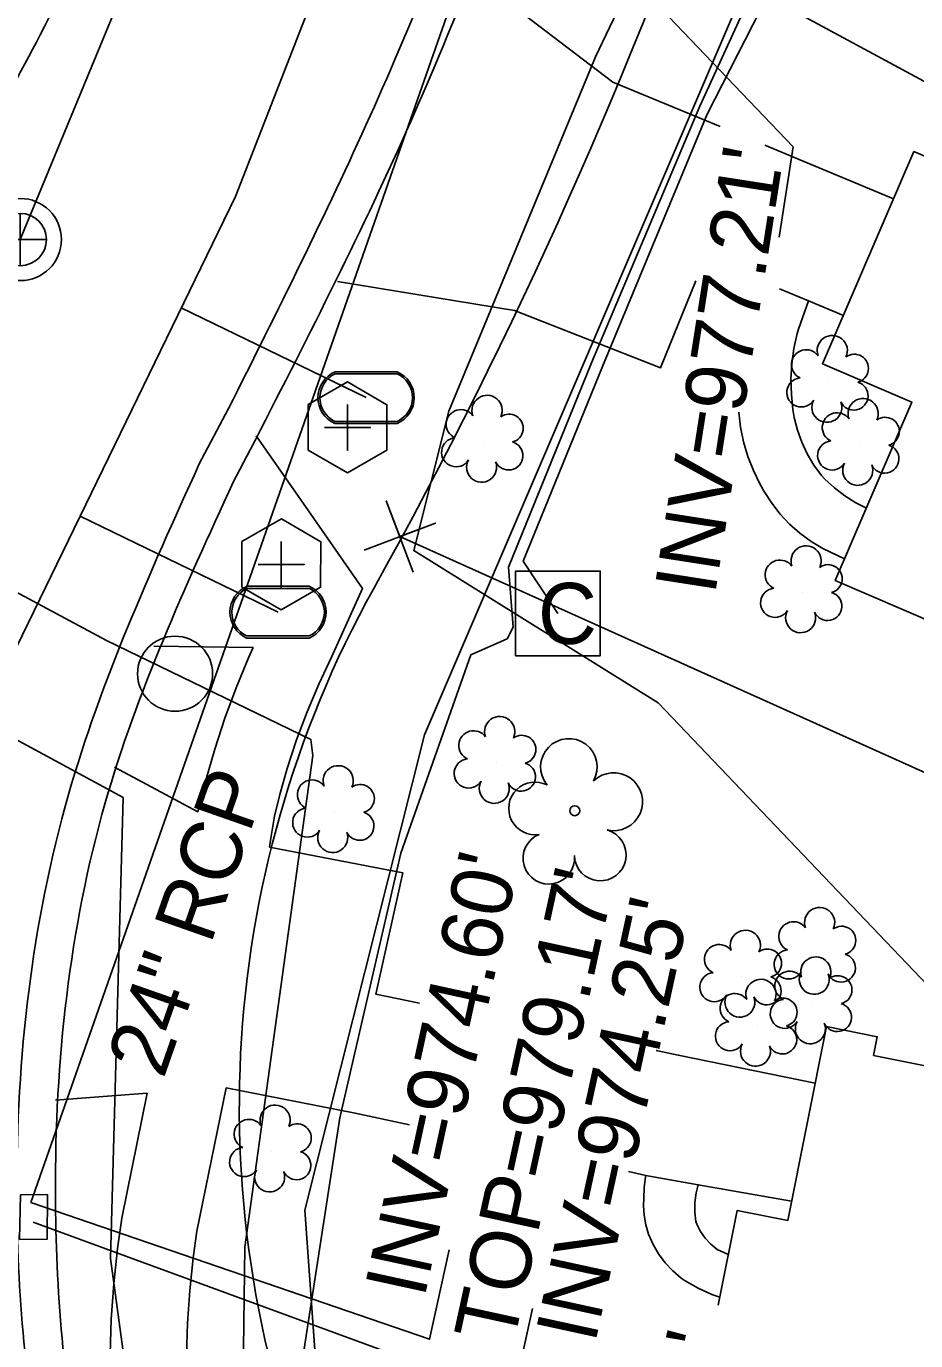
# Model space of a CAD drawing. Extents: x 1614427 to 1617186, y 896524 to 905462.
# Drawn here: x 1616388.5 to 1616446.8, y 901812.5 to 901898.7 of the extents above; entities that cross this region are included whole.
import ezdxf

# ---------------------------------------------------------------- set-up
doc = ezdxf.new("R2010")
doc.units = 0
for name, color, linetype in [('Exist Building', 7, 'Continuous'), ('Exist Other Culture Area Outline', 7, 'Continuous'), ('Exist Property Corner CELL', 7, 'Continuous'), ('Exist Property Line', 7, 'Continuous'), ('Exist Right of Way Line', 7, 'Continuous'), ('Exist Roads Curbs', 7, 'Continuous'), ('Exist Roads EOP', 7, 'Continuous'), ('Exist Roads EOP Other', 7, 'Continuous'), ('Exist Structure Minor Catch Basin', 7, 'Continuous'), ('Exist Structure Minor Catch Basin Leader', 7, 'Continuous'), ('Exist Structure Minor Catch Basin Top Elevation', 7, 'Continuous'), ('Exist Structure Minor Pipes RCP 18 Inch Invert', 7, 'Continuous'), ('Exist Structure Minor Pipes RCP 24 Inch', 7, 'Continuous'), ('Exist Structure Minor Pipes RCP 24 Inch Invert', 7, 'Continuous'), ('Exist Structure Minor Pipes RCP 24 Inch Leader', 7, 'Continuous'), ('Exist Structure Minor Pipes RCP 24 Inch Text', 7, 'Continuous'), ('Exist Utilities Gas UG Line SUE LOS B', 7, 'Continuous'), ('Exist Utilities Other Pole CELL', 7, 'Continuous'), ('Exist Utilities Power UG Cable SUE LOS B', 7, 'Continuous'), ('Exist Utilities Sanitary Sewer Clean-Out CELL', 7, 'Continuous'), ('Exist Utilities Sanitary Sewer Manhole CELL', 7, 'Continuous'), ('Exist Utilities Sanitary Sewer UG Line', 7, 'Continuous'), ('Exist Utilities Telephone UG FO SUE LOS B', 7, 'Continuous'), ('Exist Utilities TV Pedestal CELL', 7, 'Continuous'), ('Exist Utilities TV UG Cable SUE LOS B', 7, 'Continuous'), ('Exist Utilities Water Meter CELL', 7, 'Continuous'), ('Exist Utilities Water UG Line SUE LOS B', 7, 'Continuous'), ('Exist Vegetation Shrub CELL', 7, 'Continuous'), ('Exist Vegetation Tree CELL', 7, 'Continuous')]:
    doc.layers.add(name, color=color, linetype=linetype)

# ---------------------------------------------------------------- blocks, each defined once
blk = doc.blocks.new('EXIST UTILITIES SANITARY SEWER MANHOLE')
at = {"layer": 'Exist Utilities Sanitary Sewer Manhole CELL'}
blk.add_lwpolyline([(0, 0.03425), (0, -0.03425), (0, 0), (0.03425, 0), (-0.03425, 0)], dxfattribs=at)
for radius in [0.05389, 0.03425]:
    blk.add_circle((0, 0), radius, dxfattribs=at)
blk = doc.blocks.new('EXIST UTILITIES SANITARY SEWER CLEAN-OUT')
at = {"layer": 'Exist Utilities Sanitary Sewer Clean-Out CELL'}
blk.add_line((0, 0), (0, 0), dxfattribs=at)
blk.add_lwpolyline([(-0.0516, 0.0299), (-0.0517, -0.0297), (-0.0001, -0.0596), (0.0516, -0.0299), (0.0517, 0.0297), (0.0001, 0.0596)], close=True, dxfattribs=at)
blk.add_lwpolyline([(0, 0.0302), (0, -0.0302), (0, 0), (0.0302, 0), (-0.0302, 0)], dxfattribs=at)
blk = doc.blocks.new('EXIST UTILITIES WATER METER')
at = {"layer": 'Exist Utilities Water Meter CELL'}
blk.add_line((0, 0), (0, 0), dxfattribs=at)
for points in [[(-0.0408, 0.034), (0.0408, 0.034)], [(-0.0408, 0.0312), (0.0408, 0.0312)], [(0.0408, -0.0312), (-0.0413, -0.0312)], [(0.0408, -0.034), (-0.0413, -0.034)]]:
    blk.add_lwpolyline(points, dxfattribs=at)
for centre, radius, start, end in [((-0.0261, -0.0001), 0.0371, 113.178, 245.9794), ((-0.0259, -0.0001), 0.0347, 115.3009, 243.7824), ((0.0259, 0), 0.0371, 293.6483, 66.3084), ((0.0261, 0), 0.0345, 295.1272, 64.8728)]:
    blk.add_arc(centre, radius, start, end, dxfattribs=at)

msp = doc.modelspace()

# ---------------------------------------------------------------- linework, layer by layer
at = {"layer": 'Exist Building'}
msp.add_lwpolyline([(1616485.615, 901872.52), (1616475.033, 901847.931), (1616441.496, 901862.364), (1616446.524, 901874.046), (1616440.661, 901876.569), (1616446.648, 901890.482), (1616459.256, 901885.056), (1616458.823, 901884.049)], close=True, dxfattribs=at)
msp.add_lwpolyline([(1616433.826, 901814.822), (1616435.073, 901821.049), (1616438.374, 901820.388), (1616440.921, 901833.102), (1616444.246, 901832.436), (1616444.001, 901831.209), (1616477.737, 901824.452), (1616470.911, 901790.367), (1616437.689, 901797.02)], dxfattribs=at)
at = {"layer": 'Exist Other Culture Area Outline'}
for points in [[(1616443.537, 901867.106), (1616442.85, 901867.451), (1616442.12, 901867.907), (1616441.436, 901868.428), (1616440.803, 901869.009), (1616440.586, 901869.234), (1616440.09, 901869.921), (1616439.66, 901870.652), (1616439.302, 901871.419), (1616439.017, 901872.217), (1616438.808, 901873.038), (1616438.718, 901873.558), (1616438.615, 901874.558), (1616438.591, 901875.563), (1616438.647, 901876.567), (1616438.781, 901877.563), (1616438.994, 901878.545), (1616439.073, 901878.837), (1616439.738, 901880.686)], [(1616442.106, 901863.781), (1616440.675, 901864.444), (1616439.905, 901864.917), (1616439.179, 901865.455), (1616438.504, 901866.056), (1616437.885, 901866.714), (1616437.326, 901867.424), (1616436.832, 901868.181), (1616436.554, 901868.683), (1616436.125, 901869.572), (1616435.769, 901870.493), (1616435.488, 901871.44), (1616435.285, 901872.406), (1616435.161, 901873.386)], [(1616433.932, 901815.352), (1616433.412, 901815.541), (1616432.51, 901815.954), (1616431.645, 901816.438), (1616431.392, 901816.598), (1616430.842, 901817.072), (1616430.347, 901817.604), (1616429.914, 901818.187), (1616429.547, 901818.814), (1616429.25, 901819.478), (1616429.248, 901819.483), (1616429.067, 901820.093), (1616428.959, 901820.723), (1616428.925, 901821.364), (1616428.947, 901821.835), (1616428.958, 901822.549), (1616429.049, 901823.257), (1616429.065, 901823.344)], [(1616434.496, 901818.165), (1616434.391, 901818.204), (1616433.758, 901818.488), (1616433.334, 901818.823), (1616432.964, 901819.217), (1616432.655, 901819.66), (1616432.416, 901820.144), (1616432.354, 901820.31), (1616432.28, 901820.936), (1616432.285, 901821.566), (1616432.369, 901822.192), (1616432.508, 901822.728)]]:
    msp.add_lwpolyline(points, dxfattribs=at)
at = {"layer": 'Exist Property Corner CELL'}
msp.add_line((1616412.941, 901865.238), (1616412.941, 901865.238), dxfattribs=at)
msp.add_lwpolyline([(1616410.603, 901864.351), (1616415.278, 901866.125), (1616412.941, 901865.238), (1616412.054, 901867.575), (1616413.828, 901862.901)], dxfattribs=at)
at = {"layer": 'Exist Property Line'}
msp.add_line((1616412.941, 901865.238), (1616523.619, 901815.452), dxfattribs=at)
at = {"layer": 'Exist Right of Way Line'}
for centre, radius, start, end in [((1616126.099, 902020.281), 326.203, 330.93872, 10.91752), ((1616126.099, 902020.281), 276.203, 327.72922, 10.91752), ((1616472.42, 901827.828), 70, 150.93872, 203.3099)]:
    msp.add_arc(centre, radius, start, end, dxfattribs=at)
at = {"layer": 'Exist Roads Curbs'}
msp.add_line((1616402.021, 901868.809), (1616403.142, 901870.93), dxfattribs=at)
for points in [[(1616343.847, 901854.746), (1616355.943, 901862.067), (1616368.501, 901872.393), (1616373.628, 901878.463), (1616378.386, 901885.019), (1616387.13, 901899.385), (1616395.314, 901918.936), (1616406.85, 901957.62), (1616412.356, 901991.094), (1616413.858, 902015.925), (1616413.398, 902037.306), (1616411.493, 902057.132), (1616407.667, 902079.148)], [(1616403.142, 901870.93), (1616413.385, 901891.845), (1616421.355, 901911.815), (1616433.371, 901951.993), (1616439.135, 901988.052), (1616440.789, 902029.724), (1616437.241, 902067.23)], [(1616395.948, 901788.672), (1616392.138, 901803.31), (1616390.361, 901822.155), (1616393.632, 901847.778), (1616402.021, 901868.809)]]:
    msp.add_spline(points, degree=3, dxfattribs=at)
at = {"layer": 'Exist Roads EOP'}
msp.add_line((1616399.776, 901869.959), (1616401.72, 901873.638), dxfattribs=at)
for points in [[(1616345.045, 901852.485), (1616357.275, 901859.926), (1616370.331, 901870.605), (1616375.575, 901876.911), (1616380.419, 901883.477), (1616389.358, 901898.133), (1616397.69, 901918.06), (1616408.499, 901953.715), (1616414.808, 901990.97), (1616416.441, 902015.802), (1616415.921, 902037.434), (1616414.065, 902057.335), (1616410.189, 902079.521)], [(1616401.72, 901873.638), (1616410.999, 901892.827), (1616419.064, 901912.725), (1616430.933, 901952.504), (1616436.821, 901988.482), (1616438.3, 902029.711), (1616434.891, 902066.362)], [(1616393.549, 901788.008), (1616389.707, 901802.759), (1616387.829, 901822.202), (1616391.221, 901848.32), (1616399.776, 901869.959)]]:
    msp.add_spline(points, degree=3, dxfattribs=at)
at = {"layer": 'Exist Roads EOP Other'}
for points in [[(1616433.947, 901892.125), (1616426.919, 901895.044), (1616417.675, 901902.093)], [(1616445.315, 901887.384), (1616436.883, 901890.904)], [(1616432.357, 901882.001), (1616430.045, 901876.308), (1616420.459, 901880.059), (1616408.855, 901881.965)], [(1616442.024, 901879.737), (1616439.738, 901880.686), (1616437.835, 901881.476)], [(1616403.523, 901871.847), (1616406.953, 901866.924), (1616410.488, 901861.837), (1616408.47, 901857.329), (1616407.633, 901855.55), (1616406.868, 901853.739), (1616406.177, 901851.898), (1616405.561, 901850.031), (1616405.066, 901848.312), (1616404.736, 901846.893), (1616404.483, 901845.459), (1616404.401, 901844.868), (1616413.131, 901843.184), (1616411.372, 901835.217), (1616414.233, 901834.647)], [(1616394.235, 901850.114), (1616399.707, 901847.19), (1616400.218, 901849.256), (1616400.807, 901851.301), (1616401.472, 901853.323), (1616402.213, 901855.318), (1616403.028, 901857.284), (1616403.325, 901857.952), (1616396.823, 901858.049)], [(1616429.745, 901831.531), (1616431.2, 901831.235), (1616440.178, 901829.396)], [(1616390.376, 901828.272), (1616393.487, 901828.525), (1616396.383, 901828.74)], [(1616393.956, 901811.626), (1616394.028, 901813.912), (1616394.188, 901816.239), (1616394.433, 901818.55), (1616394.711, 901820.532), (1616396.383, 901828.74)], [(1616401.553, 901829.073), (1616399.641, 901819.685), (1616399.396, 901817.939), (1616399.17, 901815.804), (1616399.023, 901813.661), (1616398.955, 901811.515)], [(1616401.553, 901829.073), (1616410.011, 901827.426), (1616413.581, 901826.665)], [(1616427.936, 901823.589), (1616429.065, 901823.344), (1616429.315, 901823.29), (1616432.508, 901822.728), (1616438.627, 901821.65)]]:
    msp.add_lwpolyline(points, dxfattribs=at)
at = {"layer": 'Exist Structure Minor Catch Basin'}
msp.add_lwpolyline([(1616389.842, 901822.084), (1616388.064, 901822.056), (1616388.009, 901819.143), (1616389.827, 901819.162), (1616389.842, 901822.084)], dxfattribs=at)
at = {"layer": 'Exist Structure Minor Catch Basin Leader'}
msp.add_lwpolyline([(1616388.898, 901820.281), (1616420.361, 901808.743), (1616421.637, 901814.605)], dxfattribs=at)
at = {"layer": 'Exist Structure Minor Pipes RCP 24 Inch'}
msp.add_line((1616388.748, 901821.571), (1616419.55, 901909.43), dxfattribs=at)
msp.add_line((1616388.748, 901821.571), (1616419.55, 901909.43), dxfattribs=at)
at = {"layer": 'Exist Structure Minor Pipes RCP 24 Inch Leader'}
for points in [[(1616419.503, 901910.931), (1616438.736, 901890.792), (1616437.811, 901884.864)], [(1616388.748, 901821.571), (1616414.896, 901812.599), (1616416.173, 901818.461)]]:
    msp.add_lwpolyline(points, dxfattribs=at)
at = {"layer": 'Exist Utilities Gas UG Line SUE LOS B'}
msp.add_lwpolyline([(1616362.741, 901865.48), (1616394.795, 901848.128), (1616393.977, 901817.889), (1616396.298, 901800.873)], dxfattribs=at)
at = {"layer": 'Exist Utilities Other Pole CELL'}
msp.add_circle((1616398.209, 901856.242), 2.463, dxfattribs=at)
at = {"layer": 'Exist Utilities Power UG Cable SUE LOS B'}
for points in [[(1616453.528, 901982.946), (1616445.63, 901979.292), (1616439.321, 901941.53), (1616431.408, 901908.512), (1616425.765, 901896.685), (1616416.154, 901873.461), (1616413.852, 901864.313), (1616429.893, 901854.328), (1616452.533, 901830.598)], [(1616454.198, 901982.473), (1616452.086, 901959.007), (1616448.146, 901937.936), (1616436.912, 901904.437), (1616414.57, 901852.232), (1616406.707, 901821.065), (1616409.297, 901784.964), (1616413.113, 901774.573), (1616426.106, 901752.303), (1616435.595, 901746.317), (1616447.342, 901733.779), (1616483.503, 901710.483), (1616530.045, 901703.192), (1616556.282, 901703.485), (1616583.9, 901707.287), (1616594.216, 901733.689), (1616605.43, 901786.911), (1616617.418, 901849.024), (1616627.719, 901895.279)], [(1616432.923, 901902.872), (1616455.838, 901890.497), (1616460.593, 901886.778)]]:
    msp.add_lwpolyline(points, dxfattribs=at)
at = {"layer": 'Exist Utilities Sanitary Sewer UG Line'}
msp.add_line((1616410.5, 901939.036), (1616388.06, 901884.712), dxfattribs=at)
at = {"layer": 'Exist Utilities Telephone UG FO SUE LOS B'}
for points in [[(1616405.183, 901802.348), (1616409.015, 901827.116), (1616413.015, 901844.471), (1616417.592, 901857.479), (1616419.975, 901858.52), (1616420.384, 901859.301), (1616420.063, 901863.222), (1616425.516, 901876.625), (1616432.623, 901893.45), (1616436.62, 901902.214), (1616447.41, 901937.917), (1616451.473, 901942.162), (1616451.671, 901943.076), (1616450.182, 901945.261), (1616452.643, 901960.196), (1616453.868, 901977.593), (1616455.367, 901988.16), (1616456.764, 902019.785)], [(1616364.063, 901874.354), (1616365.498, 901873.554), (1616393.71, 901858.425), (1616407.103, 901851.936), (1616407.246, 901850.879), (1616402.792, 901818.642), (1616402.558, 901802.017)]]:
    msp.add_lwpolyline(points, dxfattribs=at)
at = {"layer": 'Exist Utilities TV Pedestal CELL'}
msp.add_line((1616423.307, 901860.195), (1616423.307, 901860.195), dxfattribs=at)
msp.add_lwpolyline([(1616420.532, 901857.42), (1616426.082, 901857.42), (1616426.082, 901862.97), (1616420.532, 901862.97), (1616420.532, 901857.42)], dxfattribs=at)
at = {"layer": 'Exist Utilities TV UG Cable SUE LOS B'}
msp.add_lwpolyline([(1616423.307, 901860.195), (1616421.035, 901863.624), (1616426.241, 901876.389), (1616433.091, 901892.926), (1616437.599, 901901.772), (1616438.32, 901902.665), (1616448.536, 901937.63), (1616453.419, 901959.852), (1616455.53, 901976.747), (1616457.243, 901978.856), (1616456.999, 901980.071), (1616456.57, 901981.798), (1616456.486, 902001.336), (1616457.199, 902019.032), (1616456.304, 902040.378), (1616454.923, 902058.172), (1616457.243, 902065.295)], dxfattribs=at)
at = {"layer": 'Exist Utilities Water UG Line SUE LOS B'}
for p, q in [((1616398.618, 901880.234), (1616410.739, 901874.347)), ((1616391.988, 901866.583), (1616404.965, 901860.28))]:
    msp.add_line(p, q, dxfattribs=at)
msp.add_lwpolyline([(1616387.062, 901856.442), (1616402.16, 901887.526), (1616412.921, 901915.139), (1616425.66, 901966.176), (1616430.701, 902016.844), (1616431.345, 902045.247), (1616429.197, 902072.396), (1616417.907, 902130.933), (1616404.63, 902193.297), (1616390.922, 902255.687), (1616390.447, 902257.774)], dxfattribs=at)
at = {"layer": 'Exist Vegetation Shrub CELL'}
for p, q in [((1616441.07, 901875.394), (1616441.07, 901875.394)), ((1616418.436, 901871.468), (1616418.436, 901871.468)), ((1616443.094, 901871.26), (1616443.094, 901871.26)), ((1616439.353, 901861.597), (1616439.353, 901861.597)), ((1616419.263, 901850.406), (1616419.263, 901850.406)), ((1616408.673, 901847.182), (1616408.673, 901847.182)), ((1616440.24, 901837.882), (1616440.24, 901837.882)), ((1616435.369, 901836.387), (1616435.369, 901836.387)), ((1616439.988, 901834.638), (1616439.988, 901834.638)), ((1616436.391, 901833.172), (1616436.391, 901833.172)), ((1616404.538, 901824.923), (1616404.538, 901824.923))]:
    msp.add_line(p, q, dxfattribs=at)
for centre, radius, start, end in [((1616441.298, 901877.434), 0.99, 334.83907, 200.47174), ((1616439.587, 901876.52), 0.968, 35.89076, 245.42165), ((1616442.742, 901876.263), 0.929, 284.45672, 126.08612), ((1616439.269, 901874.689), 0.955, 95.10992, 327.95341), ((1616442.707, 901874.465), 0.937, 204.99133, 73.46012), ((1616418.665, 901873.509), 0.99, 334.83907, 200.47174), ((1616440.941, 901873.71), 0.984, 151.27966, 21.38702), ((1616443.323, 901873.3), 0.99, 334.83907, 200.47174), ((1616416.953, 901872.595), 0.968, 35.89076, 245.42165), ((1616420.108, 901872.337), 0.929, 284.45672, 126.08612), ((1616441.611, 901872.386), 0.968, 35.89076, 245.42165), ((1616444.766, 901872.129), 0.929, 284.45672, 126.08612), ((1616416.636, 901870.764), 0.955, 95.10992, 327.95341), ((1616420.073, 901870.539), 0.937, 204.99133, 73.46012), ((1616441.294, 901870.555), 0.955, 95.10992, 327.95341), ((1616444.731, 901870.331), 0.937, 204.99133, 73.46012), ((1616418.308, 901869.785), 0.984, 151.27966, 21.38702), ((1616442.966, 901869.576), 0.984, 151.27966, 21.38702), ((1616439.582, 901863.637), 0.99, 334.83907, 200.47174), ((1616437.87, 901862.724), 0.968, 35.89076, 245.42165), ((1616441.025, 901862.466), 0.929, 284.45672, 126.08612), ((1616437.552, 901860.892), 0.955, 95.10992, 327.95341), ((1616440.99, 901860.668), 0.937, 204.99133, 73.46012), ((1616439.224, 901859.913), 0.984, 151.27966, 21.38702), ((1616419.492, 901852.446), 0.99, 334.83907, 200.47174), ((1616417.781, 901851.533), 0.968, 35.89076, 245.42165), ((1616420.935, 901851.275), 0.929, 284.45672, 126.08612), ((1616417.463, 901849.701), 0.955, 95.10992, 327.95341), ((1616408.902, 901849.222), 0.99, 334.83907, 200.47174), ((1616420.9, 901849.477), 0.937, 204.99133, 73.46012), ((1616407.19, 901848.309), 0.968, 35.89076, 245.42165), ((1616410.345, 901848.051), 0.929, 284.45672, 126.08612), ((1616419.135, 901848.722), 0.984, 151.27966, 21.38702), ((1616406.873, 901846.478), 0.955, 95.10992, 327.95341), ((1616410.31, 901846.253), 0.937, 204.99133, 73.46012), ((1616408.545, 901845.498), 0.984, 151.27966, 21.38702), ((1616440.469, 901839.923), 0.99, 334.83907, 200.47174), ((1616438.758, 901839.009), 0.968, 35.89076, 245.42165), ((1616441.912, 901838.751), 0.929, 284.45672, 126.08612), ((1616435.597, 901838.427), 0.99, 334.83907, 200.47174), ((1616433.886, 901837.514), 0.968, 35.89076, 245.42165), ((1616437.041, 901837.256), 0.929, 284.45672, 126.08612), ((1616438.44, 901837.178), 0.955, 95.10992, 327.95341), ((1616441.877, 901836.953), 0.937, 204.99133, 73.46012), ((1616440.217, 901836.679), 0.99, 334.83907, 200.47174), ((1616433.568, 901835.683), 0.955, 95.10992, 327.95341), ((1616436.62, 901835.213), 0.99, 334.83907, 200.47174), ((1616437.006, 901835.458), 0.937, 204.99133, 73.46012), ((1616438.505, 901835.765), 0.968, 35.89076, 245.42165), ((1616440.112, 901836.199), 0.984, 151.27966, 21.38702), ((1616441.66, 901835.507), 0.929, 284.45672, 126.08612), ((1616434.908, 901834.299), 0.968, 35.89076, 245.42165), ((1616435.24, 901834.703), 0.984, 151.27966, 21.38702), ((1616438.188, 901833.934), 0.955, 95.10992, 327.95341), ((1616438.063, 901834.041), 0.929, 284.45672, 126.08612), ((1616441.625, 901833.709), 0.937, 204.99133, 73.46012), ((1616434.591, 901832.468), 0.955, 95.10992, 327.95341), ((1616439.86, 901832.955), 0.984, 151.27966, 21.38702), ((1616438.028, 901832.243), 0.937, 204.99133, 73.46012), ((1616436.263, 901831.488), 0.984, 151.27966, 21.38702), ((1616404.767, 901826.964), 0.99, 334.83907, 200.47174), ((1616403.055, 901826.05), 0.968, 35.89076, 245.42165), ((1616406.21, 901825.792), 0.929, 284.45672, 126.08612), ((1616402.738, 901824.219), 0.955, 95.10992, 327.95341), ((1616406.175, 901823.994), 0.937, 204.99133, 73.46012), ((1616404.41, 901823.239), 0.984, 151.27966, 21.38702)]:
    msp.add_arc(centre, radius, start, end, dxfattribs=at)
at = {"layer": 'Exist Vegetation Tree CELL'}
msp.add_line((1616424.414, 901847.256), (1616424.414, 901847.256), dxfattribs=at)
msp.add_circle((1616424.414, 901847.256), 0.326, dxfattribs=at)
for centre, radius, start, end in [((1616424.029, 901850.129), 1.856, 330.16508, 219.71335), ((1616421.809, 901847.41), 1.727, 62.66361, 279.3457), ((1616426.963, 901847.845), 1.899, 257.1011, 134.19993), ((1616422.71, 901844.135), 1.689, 111.56708, 6.23104), ((1616426.087, 901844.357), 1.698, 181.28216, 74.55999)]:
    msp.add_arc(centre, radius, start, end, dxfattribs=at)

# ---------------------------------------------------------------- block references
at = {"layer": 'Exist Utilities Sanitary Sewer Clean-Out CELL', "xscale": 50, "yscale": 50}
for p in [(1616409.511, 901872.396), (1616405.171, 901863.411)]:
    msp.add_blockref('EXIST UTILITIES SANITARY SEWER CLEAN-OUT', p, dxfattribs=at)
at = {"layer": 'Exist Utilities Sanitary Sewer Manhole CELL', "xscale": 50, "yscale": 50}
msp.add_blockref('EXIST UTILITIES SANITARY SEWER MANHOLE', (1616388.06, 901884.712), dxfattribs=at)
at = {"layer": 'Exist Utilities Water Meter CELL', "xscale": 50, "yscale": 50}
for p in [(1616410.739, 901874.347), (1616404.965, 901860.28)]:
    msp.add_blockref('EXIST UTILITIES WATER METER', p, dxfattribs=at)

# ---------------------------------------------------------------- texts
at = {"layer": 'Exist Structure Minor Catch Basin Top Elevation'}
for s, p in [("TOP=979.17'", (1616420.387, 901812.142)), ("TOP=978.02'", (1616427.755, 901781.821))]:
    msp.add_text(s, height=4, rotation=77.71667, dxfattribs=at).set_placement(p)
at = {"layer": 'Exist Structure Minor Pipes RCP 18 Inch Invert'}
msp.add_text("INV=977.21'", height=4, rotation=81.13577, dxfattribs=at).set_placement((1616433.605, 901861.335))
at = {"layer": 'Exist Structure Minor Pipes RCP 24 Inch Invert'}
for s, p in [("INV=974.60'", (1616414.547, 901815.216)), ("INV=974.25'", (1616425.743, 901812.244))]:
    msp.add_text(s, height=4, rotation=77.71667, dxfattribs=at).set_placement(p)
at = {"layer": 'Exist Structure Minor Pipes RCP 24 Inch Text'}
msp.add_text('24" RCP', height=4, rotation=70.68013, dxfattribs=at).set_placement((1616397.441, 901829.607))
at = {"layer": 'Exist Utilities TV Pedestal CELL'}
msp.add_text('C', height=4, dxfattribs=at).set_placement((1616422, 901858.195))

doc.saveas('drawing.dxf')
